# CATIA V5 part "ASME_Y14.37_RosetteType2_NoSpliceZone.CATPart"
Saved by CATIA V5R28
Part number: 333X3333-303
Revision: --
Nomenclature: ASME_Y14.37_RosetteType2
Bounding box of the stored display mesh (mm): x -188.298 to 149.059, y -714.612 to 664.697, z 0 to 91.639
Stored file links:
  C:\Users\jvl2147\Documents\AP242 testing\Composite Example Parts for PER\ASME_Y14.37_RosetteType2_NoSpliceZone.CATPart
  \\NW\Data\MSE-Composites\ASME Y14.37\ASME Y-14.37_COMPOSITES.CATMaterial
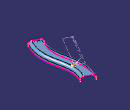
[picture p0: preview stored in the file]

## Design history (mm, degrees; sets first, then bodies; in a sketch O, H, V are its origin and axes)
AxisSystem1 "ROSETTE COORDINATE SYSTEM": origin (-72.9205, -637.9645, 93.98), X (0.5026, 0.8645, 0), Y (-0.8645, 0.5026, 0), Z (0, 0, 1)
CompParametersFeature1 "CATCoParametersFeatName": Value 0, Value 45, Value -45, Value 90
CompEOPGroupFeature1 "CATCoEOPGroupFeatName"
CompStacking1 "Stacking"
CompIsoThickAreasGroup1 "CATCoIsoThickAreasGroupFeatName": RefAddThickness 0
TTRSSet1
f4a2d38f3ddc11d3a929006094b99c4b_11 "CATTPSSet"
CompReviewTools1 "Review tools"
Set1 "CONSTRUCTION GEOMETRY"
  Set2 "CONSTRUCTION - LAMINATE REFERENCE SURFACE"
    Sketch1 on xy-plane, origin (0, 0, 0), H (1, 0, 0), V (0, 1, 0)
      spline S1 through (-79.505, -649.09) (21.2912, -260.3998) (-51.6257, 228.8061) (37.963, 602.845)
    Plane1: type Normal, Curve Sketch1, RefPoint vertex of Sketch1, Ratio 0
    Sketch2 on Plane1, origin (-464.3095, -417.3341, 0), H (-0.8566, 0.5159, 0), V (0, 0, 1)
      line L1 (-525.4052, 91.6386) -> (-373.0052, 91.6386)
      line L2 (-322.2052, 40.8386) -> (-322.2052, 0)
      line L3 (-576.2052, 0) -> (-576.2052, 40.8386)
      reference projected point E1 (-449.2052, 0) from vertex of Sketch1
      reference projected point E2 (-449.2052, 0) from vertex of Sketch1
      arc A1 centre (-373.0052, 40.8386) radius 50.8 from (-373.0052, 91.6386) to (-322.2052, 40.8386) cw
      arc A2 centre (-525.4052, 40.8386) radius 50.8 from (-576.2052, 40.8386) to (-525.4052, 91.6386) cw
      distance E1 L2 = 127
      distance E2 L3 = 127
      radius A1 = 50.8
      radius A2 = 50.8
      horizontal: L1 H
      vertical: L2 V, L3 V
      tangency: A1 L1, A1 L2, A2 L3, A2 L1
    Sweep1: type Unspec, Profile Sketch2, Guide Sketch1
  Set3 "CONSTRUCTION - PLIES EOPS"
    Plane2: type Normal, Curve Sketch1, RefPoint vertex of Sketch1, Ratio 0
    Plane3: type Normal, Curve Sketch1, RefPoint {point type OnCurve, Support Sketch1, Length 1118.262}, Ratio 0.99
    Plane4: type Normal, Curve Sketch1, Ratio 0.01
    Intersect1: ToIntersect1 Plane3, ToIntersect2 Sweep1
    Intersect2: ToIntersect1 Sweep1, ToIntersect2 Plane4
    Plane5: type Offset, RefPlane xy-plane, Offset 2.54
    Intersect3: ToIntersect1 Plane5, ToIntersect2 Join1
    Near1: MultiElement Intersect3, ReferenceElement edge of Sweep1
    Near2: MultiElement Intersect3, ReferenceElement edge of Sweep1
  Set4 "CONSTRUCTION - ROSETTE COORDINATE SYSTEM"
    Intersect4: ToIntersect1 Plane4, ToIntersect2 Project2
    Line1: type Tangency, RefPoint Intersect4, Curve Project2, Start 0, End 25.4
    Plane6: type Offset, RefPlane xy-plane, Offset 93.98
    Project1 "PROJECT": ToProject Sketch1, Support Join1, Direction xy-plane
  Set5 "CONSTRUCTION - ROSETTE TRANSFORMS"
    Line2 "Ply.1_Rosette_transfer_X": type Tangency, RefPoint {point type OnCurve, Support Project2, Length 288.56}, Curve Project2, Support Join1, Start 0, End 25.4
    Line3 "Ply.1_Rosette_transfer_X.Renamed": type Tangency, RefPoint {point type OnCurve, Support Project2, Length 536.186}, Curve Project2, Support Join1, Start 25.4, End 0
    Line4 "Ply.1_Rosette_transfer_X.Renamed": type Tangency, RefPoint {point type OnCurve, Support Project2, Length 783.62}, Curve Project2, Support Join1, Start 25.4, End 0
    Line5 "Ply.1_Rosette_transfer_X.Renamed": type Tangency, RefPoint {point type OnCurve, Support Project2, Length 1274.71}, Curve Project2, Support Join1, Start 25.4, End 0
    Line6 "Ply.1_Rosette_transfer_X.Renamed": type Tangency, RefPoint {point type OnCurve, Support Project2, Length 1017.245}, Curve Project2, Support Join1, Start 25.4, End 0
    AxisSystem2 "ROSETTE COORDINATE SYSTEM": origin (16.8931, -379.3831, 93.98), X (0.1242, 0.9923, 0), Y (-0.9923, 0.1242, 0), Z (0, 0, 1)
    AxisSystem3 "ROSETTE COORDINATE SYSTEM.Renamed": origin (7.1166, -132.8437, 93.98), X (-0.1632, 0.9866, 0), Y (-0.9866, -0.1632, 0), Z (0, 0, 1)
    AxisSystem4 "ROSETTE COORDINATE SYSTEM.Renamed1": origin (-38.9217, 110.2518, 93.98), X (-0.1571, 0.9876, 0), Y (-0.9876, -0.1571, 0), Z (0, 0, 1)
    AxisSystem5 "ROSETTE COORDINATE SYSTEM.Renamed2": origin (29.3229, 586.9432, 93.98), X (0.4677, 0.8839, 0), Y (-0.8839, 0.4677, 0), Z (0, 0, 1)
    AxisSystem6 "ROSETTE COORDINATE SYSTEM.Renamed3": origin (-47.995, 342.9553, 93.98), X (0.1137, 0.9935, 0), Y (-0.9935, 0.1137, 0), Z (0, 0, 1)
    Point1: type OnSurface, Support Join1, Length 362.156, Direction (-0.4364, -0.3881, 0.8118)
    Line7: type Normal, RefPoint Point1, RefSkin Join1, Start 254, End 0
  Plane7: type Offset, RefPlane YZ plane of AxisSystem2, Offset 0
  Circle1: type CtrRad, Start 0, End 180, Center {point type OnSurface, Support Join1, Length 336.531, Direction (0.5738, 0.5102, 0.6407)}, Support Join1, Radius 50.8, FirstDirection (1, 0, 0)
  CurvePar1: Offset Near1, Support Join1, Offset2 0, Offset1 50.8
Set6 "ENGINEERING GEOMETRY"
  Set7 "LAMINATE REFERENCE SURFACE"
    Join1 "LAMINATE REFERENCE SURFACE": Elements Sweep1
  Set8 "GUIDE CURVE - ZERO DEGREE ORIENTATION"
    Project2 "GUIDE CURVE - 0°": ToProject Sketch1, Support Plane6
Body1 (main body)
Body2 "-303"
  CompIsoThickAreasSolid1 "Area Solid.1": IsoAreasGroup CompIsoThickAreasGroup1
Set9 "Workaround For FT&A"
  Split1 "Surface For FT&A": ToCut Join1
Set10 "Workaround For FT&A"
  Split2 "Surface For FT&A": ToCut Join1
